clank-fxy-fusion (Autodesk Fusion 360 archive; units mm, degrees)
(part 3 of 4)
sketch "Limit Wire Clip" plane through (0, 0, 0) normal (0, 0, -1) x axis (1, 0, 0)
  line L1 (79.8, -13) -> (66.15, -13)
  line L2 (79.8, -9) -> (79.8, -13)
  line L3 (100.2, -9) -> (79.8, -9)
  line L4 (100.2, -12.5) -> (100.2, -9)
  line L5 (100.7, -13) -> (100.2, -12.5)
  line L6 (102.8, -13) -> (100.7, -13)
  line L7 (102.8, 5.7) -> (102.8, -13)
  line L8 (117, 5.7) -> (102.8, 5.7)
  line L9 (117, 17.5) -> (117, 5.7)
  line L10 (103, 17.5) -> (117, 17.5)
  line L11 (103, 32.35) -> (103, 17.5)
  line L12 (57.65, 32.35) -> (103, 32.35)
  line L13 (57.65, 16.96) -> (57.65, 32.35)
  line L14 (77.0815, 16.46) -> (58.15, 16.46)
  line L15 (58.15, 15.46) -> (77.0815, 15.46)
  line L16 (56.65, 23.55) -> (56.65, 16.96)
  line L17 (2.85, 23.55) -> (56.65, 23.55)
  line L18 (2.85, 8.85) -> (2.85, 23.55)
  line L19 (14.2, 8.85) -> (2.85, 8.85)
  line L20 (14.2, -13) -> (14.2, 8.85)
  line L21 (2.85, -13) -> (14.2, -13)
  line L22 (2.85, -37.1) -> (2.85, -13)
  line L23 (56.65, -37.1) -> (2.85, -37.1)
  line L24 (56.65, -25.4747) -> (56.65, -37.1)
  line L25 (66.15, -25.4747) -> (56.65, -25.4747)
  line L26 (66.15, -13) -> (66.15, -25.4747)
  line L27 (6.5983, -31) -> (11.1017, -31)
  line L28 (4.3467, -27.1) -> (6.5983, -31)
  line L29 (6.5983, -23.2) -> (4.3467, -27.1)
  line L30 (11.1017, -23.2) -> (6.5983, -23.2)
  line L31 (13.3533, -27.1) -> (11.1017, -23.2)
  line L32 (11.1017, -31) -> (13.3533, -27.1)
  line L33 (24.7517, 9.65) -> (27.0033, 13.55)
  line L34 (20.2483, 9.65) -> (24.7517, 9.65)
  line L35 (17.9967, 13.55) -> (20.2483, 9.65)
  line L36 (20.2483, 17.45) -> (17.9967, 13.55)
  line L37 (24.7517, 17.45) -> (20.2483, 17.45)
  line L38 (27.0033, 13.55) -> (24.7517, 17.45)
  line L39 (49.7517, 9.65) -> (52.0033, 13.55)
  line L40 (45.2483, 9.65) -> (49.7517, 9.65)
  line L41 (42.9967, 13.55) -> (45.2483, 9.65)
  line L42 (45.2483, 17.45) -> (42.9967, 13.55)
  line L43 (49.7517, 17.45) -> (45.2483, 17.45)
  line L44 (52.0033, 13.55) -> (49.7517, 17.45)
  line L45 (77.0815, 29.81) -> (73.0815, 29.81)
  line L46 (77.5815, 19.5) -> (77.5815, 29.31)
  line L47 (73.0815, 19) -> (77.0815, 19)
  line L48 (72.5815, 29.31) -> (72.5815, 19.5)
  line L49 (32.7483, 14.65) -> (37.2517, 14.65)
  line L50 (30.4967, 18.55) -> (32.7483, 14.65)
  line L51 (32.7483, 22.45) -> (30.4967, 18.55)
  line L52 (37.2517, 22.45) -> (32.7483, 22.45)
  line L53 (39.5033, 18.55) -> (37.2517, 22.45)
  line L54 (37.2517, 14.65) -> (39.5033, 18.55)
  line L55 (6.5983, 12.3) -> (11.1017, 12.3)
  line L56 (4.3467, 16.2) -> (6.5983, 12.3)
  line L57 (6.5983, 20.1) -> (4.3467, 16.2)
  line L58 (11.1017, 20.1) -> (6.5983, 20.1)
  line L59 (13.3533, 16.2) -> (11.1017, 20.1)
  line L60 (11.1017, 12.3) -> (13.3533, 16.2)
  line L61 (65.6533, -19.4747) -> (63.4017, -15.5747)
  line L62 (63.4017, -23.3747) -> (65.6533, -19.4747)
  line L63 (58.8983, -23.3747) -> (63.4017, -23.3747)
  line L64 (56.6467, -19.4747) -> (58.8983, -23.3747)
  line L65 (58.8983, -15.5747) -> (56.6467, -19.4747)
  line L66 (63.4017, -15.5747) -> (58.8983, -15.5747)
  line L67 (1.35, -31.1) -> (2.85, -31.1)
  line L68 (1.35, -35.1) -> (1.35, -31.1)
  line L69 (-1.95, -37.1) -> (1.85, -37.1)
  line L70 (-1.95, -26.1) -> (-1.95, -37.1)
  line L71 (2.85, -26.1) -> (-1.95, -26.1)
  line L72 (1.85, -35.1) -> (1.35, -35.1)
  line L73 (1.85, -37.1) -> (1.85, -35.1)
  line L74 (79.8, -25.4747) -> (66.15, -25.4747)
  line L75 (79.8, -13) -> (79.8, -25.4747)
  line L76 (79.8, -32) -> (79.8, -25.4747)
  line L77 (56.65, -32) -> (79.8, -32)
  line L78 (80.2, -32) -> (79.8, -32)
  line L79 (80.2, -22) -> (80.2, -32)
  line L80 (79.8, -22) -> (80.2, -22)
  arc A1 centre (58.15, 16.96) radius 0.5 clockwise from (58.15, 16.46) to (57.65, 16.96)
  arc A2 centre (77.0815, 15.96) radius 0.5 clockwise from (77.0815, 16.46) to (77.0815, 15.46)
  arc A3 centre (58.15, 16.96) radius 1.5 clockwise from (58.15, 15.46) to (56.65, 16.96)
  circle C1 centre (66, -6.5) radius 2.125
  circle C2 centre (66, 26.35) radius 2.125
  arc A4 centre (73.0815, 29.31) radius 0.5 clockwise from (72.5815, 29.31) to (73.0815, 29.81)
  arc A5 centre (77.0815, 29.31) radius 0.5 clockwise from (77.0815, 29.81) to (77.5815, 29.31)
  arc A6 centre (77.0815, 19.5) radius 0.5 clockwise from (77.5815, 19.5) to (77.0815, 19)
  arc A7 centre (73.0815, 19.5) radius 0.5 clockwise from (73.0815, 19) to (72.5815, 19.5)
  arc A8 centre (35, -15.45) radius 8.5 clockwise from (43.4011, -16.743) to (26.5989, -14.157)
  arc A9 centre (61.15, -19.4747) radius 34.9579 clockwise from (26.5989, -14.157) to (26.9246, -12.356)
  arc A10 centre (35.2465, -14.0869) radius 8.5 clockwise from (26.9246, -12.356) to (43.5684, -15.8178)
  arc A11 centre (61.15, -19.4747) radius 17.9579 clockwise from (43.4011, -16.743) to (43.5684, -15.8178)
  circle C3 centre (24.0415, -7) radius 2.125
  point P92 (2.85, -31.1)
  point P97 (2.85, -26.1)
  point P30 (2.85, -37.1)
  point P94 (1.85, -37.1)
  point P100 (1.85, -37.1)
  point P33 (66.15, -25.4747)
  point P102 (66.15, -25.4747)
  point P3 (79.8, -13)
  point P104 (79.8, -13)
  point P106 (56.65, -32)
  point P109 (79.8, -22)
  point P93 (1.35, -31.1)
  point P99 (1.85, -35.1)
  point P98 (1.35, -35.1)
  point P107 (80.2, -32)
  point P108 (80.2, -22)
  point P110 (90, -1)
  coincident L22 P92
  perpendicular L22 L67
  perpendicular L67 L68
  perpendicular L68 L69
  perpendicular L69 L70
  coincident L22 P97
  perpendicular L22 L71
  coincident P30 L69
  perpendicular L22 L72
  perpendicular L72 L73
  coincident P94 P100
  coincident P33 P102
  perpendicular L26 L74
  perpendicular L74 L75
  coincident P3 P104
  perpendicular L74 L76
  coincident L24 P106
  perpendicular L24 L77
  perpendicular L76 L78
  perpendicular L78 L79
  coincident L75 P109
  perpendicular L75 L80
  dimension "d1771" distance P30 P97 = 11
  dimension "d1772" distance P92 P93 = 1.5
  dimension "d1773" distance P30 L73 = 1
  dimension "d1774" distance L67 P97 = 5
  dimension "d1775" distance P99 P100 = 2
  dimension "d1776" distance P93 P98 = 4
  dimension "d1777" distance L70 P98 = 3.3
  dimension "d1791" distance P104 L77 = 19
  dimension "d1813" distance P107 P108 = 10
  dimension "d1814" distance L79 P110 = 9.8
extrude "Extrude122" add sketch "Limit Wire Clip" profile of L22 L67 L68 L69 L70 L71 L72 L73 against normal blind 5
extrude "Extrude123" new body sketch "Limit Wire Clip" profile of L1 L24 L25 L26 L74 L75 L76 L77 L78 L79 L80 to an object
chamfer "Chamfer21" distance 1
combine "Combine20"
fillet "Fillet52" radius 0.5
fillet "Fillet57" radius 0.5
fillet "Fillet40" radius 2.2
fillet "Fillet41" radius 2
fillet "Fillet58" radius 1
fillet "Fillet43" radius 1
fillet "Fillet44" radius 5
fillet "Fillet45" radius 2
fillet "Fillet46" radius 1
fillet "Fillet47" radius 2
fillet "Fillet48" radius 1
fillet "Fillet49" radius 2
fillet "Fillet50" radius 1
fillet "Fillet51" radius 2
fillet "Fillet59" radius 0.5
fillet "Fillet60" radius 1
fillet "Fillet61" radius 1
sketch "Motor Cable Clip" plane through (0, 0, 30.7) normal (0, 0, 1) x axis (-1, 0, 0)
  line L1 (-15.084, 6.3745) -> (-14.3541, 20.3023)
  line L2 (-53.5453, 6.1872) -> (-17.3961, 4.2927)
  line L3 (-61.7085, 2.3499) -> (-57.6468, 2.3499)
  line L4 (-66.0474, -6.3422) -> (-63.6058, 0.9823)
  line L5 (-66.15, -23.4747) -> (-66.15, -6.9747)
  line L6 (-58.85, -25.4747) -> (-64.15, -25.4747)
  line L7 (-56.65, -35.1) -> (-56.65, -27.6747)
  line L8 (-4.85, -37.1) -> (-54.65, -37.1)
  line L9 (-2.85, 20.25) -> (-2.85, -35.1)
  line L10 (-13.3555, 21.25) -> (-3.85, 21.25)
  line L11 (-11.85, 2.5624) -> (2.15, -21.6863)
  line L12 (-5.7878, 6.0624) -> (-11.85, 2.5624)
  line L13 (8.2122, -18.1863) -> (-5.7878, 6.0624)
  line L14 (2.15, -21.6863) -> (8.2122, -18.1863)
  line L15 (-13.85, 5.7) -> (-13.85, -36.6)
  line L16 (-1.5517, -23.8235) -> (2.15, -21.6863)
  line L17 (-11.85, 2.5624) -> (-11.85, -19.6838)
  line L18 (-2.85, -24.573) -> (-1.5517, -23.8235)
  arc A1 centre (-13.3555, 20.25) radius 1 clockwise from (-14.3541, 20.3023) to (-13.3555, 21.25)
  arc A2 centre (-17.281, 6.4897) radius 2.2 clockwise from (-15.084, 6.3745) to (-17.3961, 4.2927)
  arc A3 centre (-61.7085, 0.3499) radius 2 clockwise from (-63.6058, 0.9823) to (-61.7085, 2.3499)
  arc A4 centre (-64.15, -6.9747) radius 2 clockwise from (-66.15, -6.9747) to (-66.0474, -6.3422)
  arc A5 centre (-64.15, -23.4747) radius 2 clockwise from (-64.15, -25.4747) to (-66.15, -23.4747)
  arc A6 centre (-58.85, -27.6747) radius 2.2 clockwise from (-58.85, -25.4747) to (-56.65, -27.6747)
  arc A7 centre (-54.65, -35.1) radius 2 clockwise from (-54.65, -37.1) to (-56.65, -35.1)
  arc A8 centre (-4.85, -35.1) radius 2 clockwise from (-2.85, -35.1) to (-4.85, -37.1)
  arc A9 centre (-3.85, 20.25) radius 1 clockwise from (-3.85, 21.25) to (-2.85, 20.25)
  circle C1 centre (-61.15, -19.4747) radius 2.125
  arc A10 centre (-9.3208, -29.8267) radius 2.125 clockwise from (-7.2369, -30.2429) to (-11.4046, -29.4105)
  arc A11 centre (-61.15, -19.4747) radius 50.728 clockwise from (-10.9528, -26.7934) to (-11.4046, -29.4105)
  arc A12 centre (-8.85, -27.1) radius 2.125 clockwise from (-10.9528, -26.7934) to (-6.7472, -27.4066)
  arc A13 centre (-61.15, -19.4747) radius 54.978 clockwise from (-6.7472, -27.4066) to (-7.2369, -30.2429)
  circle C2 centre (-19.5, 0.05) radius 1.625
  circle C3 centre (-35, -15.45) radius 11.05
  circle C4 centre (-19.5, -30.95) radius 1.625
  circle C5 centre (-50.5, 0.05) radius 1.625
  arc A14 centre (-7.0546, 13.4139) radius 2.125 clockwise from (-5.2389, 14.5179) to (-8.8704, 12.31)
  arc A15 centre (-61.15, -19.4747) radius 61.1836 clockwise from (-10.6055, 15.0026) to (-8.8704, 12.31)
  arc A16 centre (-8.85, 16.2) radius 2.125 clockwise from (-10.6055, 15.0026) to (-7.0945, 17.3974)
  arc A17 centre (-61.15, -19.4747) radius 65.4336 clockwise from (-7.0945, 17.3974) to (-5.2389, 14.5179)
  circle C6 centre (-50.5, -30.95) radius 1.625
  arc A18 centre (-8.85, -27.1) radius 8 clockwise from (-11.85, -19.6838) to (-1.5517, -23.8235)
  arc A19 centre (-8.85, -27.1) radius 5 clockwise from (-13.7977, -26.3786) to (-3.9023, -27.8214)
  arc A20 centre (-53.65, 4.1899) radius 2 clockwise from (-55.6484, 4.2699) to (-53.5453, 6.1872)
  arc A21 centre (-57.6468, 4.3499) radius 2 clockwise from (-55.6484, 4.2699) to (-57.6468, 2.3499)
  point P49 (-8.85, -27.1)
  point P59 (-8.85, -27.1)
  point P61 (-2.85, -24.573)
  point P50 (-7.0546, 13.4139)
  point P53 (-11.85, 2.5624)
  point P52 (2.15, -21.6863)
  point P55 (8.2122, -18.1863)
  perpendicular L11 L12
  parallel L11 L13
  parallel L12 L14
  perpendicular L11 L16
  coincident P49 P59
  vertical L17
  coincident L9 P61
  parallel L16 L18
  dimension "d1818" angle L9 L13 = 30
  dimension "d1819" distance P50 L12 = 7
  dimension "d1820" distance P53 L15 = 2
  dimension "d1822" distance P52 P55 = 7
  dimension "d1823" distance P52 P53 = 28
  dimension "d1854" distance A18 A19 = 3
extrude "Extrude127" add sketch "Motor Cable Clip" profile of L9 L11 L13 L14 L16 A18 L18 to an object
extrude "Extrude128" add sketch "Motor Cable Clip" profile of L9 L11 L12 L13 L14 L16 A18 L17 along normal blind 51
sketch "Sketch32" plane through (1.7158, 0.9906, 0) normal (-0.866, -0.5, 0) x axis (0.5, -0.866, 0)
  line L1 (2.2685, 24.7) -> (-19.8559, 24.7)
  line L2 (2.2685, 30.7) -> (2.2685, 24.7)
  line L3 (8.1441, 30.7) -> (2.2685, 30.7)
  line L4 (8.1441, 81.7) -> (8.1441, 30.7)
  line L5 (-19.8559, 81.7) -> (8.1441, 81.7)
  line L6 (-19.8559, 24.7) -> (-19.8559, 81.7)
  line L7 (-1.8559, 34.2) -> (-1.8559, 78.2)
  circle C1 centre (-1.8559, 78.2) radius 1.35
  circle C2 centre (-1.8559, 34.2) radius 1.35
  point P8 (-1.8559, 78.2)
  point P10 (-1.8559, 78.2)
  point P9 (-1.8559, 34.2)
  point P11 (-1.8559, 34.2)
  point P6 (8.1441, 81.7)
  vertical L7
  coincident P8 P10
  coincident P9 P11
  equal C1 C2
  dimension "d2013" distance P8 P9 = 44
  dimension "d2014" diameter C1 = 2.7
  dimension "d2015" distance L5 P10 = 3.5
  dimension "d2016" distance P6 L7 = 10
extrude "Extrude137" cut sketch "Sketch32" profile of C1 C2 to an object
fillet "Fillet69" radius 2
chamfer "Chamfer18" distance 2
component_insert "Component Insert72"
joint "Assemble72" alignAngle 0 alignOffsetX 0 alignOffsetY 0 alignOffsetZ 0
component_insert "Component Insert73"
joint "Assemble73" alignAngle 0 alignOffsetX 0 alignOffsetY 0 alignOffsetZ -17.5
component_insert "Component Insert74"
joint "Assemble74" alignAngle 0 alignOffsetX 0 alignOffsetY 0 alignOffsetZ 0
component_insert "Component Insert75"
joint "Assemble75" alignAngle 0 alignOffsetX 0 alignOffsetY 0 alignOffsetZ 0
component_insert "Component Insert76"
joint "Assemble76" alignAngle 0 alignOffsetX 0 alignOffsetY 0 alignOffsetZ 0
component_insert "Component Insert77"
joint "Assemble77" alignAngle 0 alignOffsetX 0 alignOffsetY 0 alignOffsetZ 0
component_insert "Component Insert79"
joint "Assemble79" alignAngle 30 alignOffsetX 0 alignOffsetY 0 alignOffsetZ -1.5
component_insert "Component Insert80"
joint "Assemble80" alignAngle 0 alignOffsetX 0 alignOffsetY 0 alignOffsetZ 0
component_insert "Component Insert81"
joint "Assemble81" alignAngle 0 alignOffsetX 0 alignOffsetY 0 alignOffsetZ 0
component_insert "Component Insert82"
joint "Assemble82" alignAngle 0 alignOffsetX 0 alignOffsetY 0 alignOffsetZ 0
component_insert "Component Insert78"
joint "Assemble78" alignAngle 30 alignOffsetX 0 alignOffsetY 0 alignOffsetZ -1.5
component_insert "Component Insert85"
joint "Assemble84" alignAngle 0 alignOffsetX 0 alignOffsetY 0 alignOffsetZ 0
component_insert "Component Insert84"
joint "Assemble85" alignAngle 0 alignOffsetX 0 alignOffsetY 0 alignOffsetZ 0
component_insert "Component Insert86"
joint "Assemble86" alignAngle 0 alignOffsetX 0 alignOffsetY 0 alignOffsetZ 0
component_insert "Component Insert87"
joint "Assemble87" alignAngle 0 alignOffsetX 0 alignOffsetY 0 alignOffsetZ 0
component_insert "Component Insert88"
joint "Assemble88" alignAngle 0 alignOffsetX 0 alignOffsetY 0 alignOffsetZ 0
component_insert "Component Insert89"
joint "Assemble89" alignAngle 0 alignOffsetX 0 alignOffsetY 0 alignOffsetZ 0
component_insert "Component Insert92"
joint "Assemble92" alignAngle 0 alignOffsetX 0 alignOffsetY 0 alignOffsetZ 0
component_insert "Component Insert93"
joint "Assemble93" alignAngle 0 alignOffsetX 0 alignOffsetY 0 alignOffsetZ 0
component_insert "Component Insert94"
joint "Assemble94" alignAngle 0 alignOffsetX 0 alignOffsetY 0 alignOffsetZ 0
component_insert "Component Insert95"
joint "Assemble95" alignAngle 0 alignOffsetX 0 alignOffsetY 0 alignOffsetZ 0
component_insert "Component Insert96"
joint "Assemble96" alignAngle 0 alignOffsetX 0 alignOffsetY 0 alignOffsetZ 0
component_insert "Component Insert97"
joint "Assemble97" alignAngle 0 alignOffsetX 0 alignOffsetY 0 alignOffsetZ 0
component_insert "Component Insert98"
joint "Assemble98" alignAngle 0 alignOffsetX 0 alignOffsetY 0 alignOffsetZ 0
component_insert "Component Insert99"
joint "Assemble99" alignAngle 0 alignOffsetX 0 alignOffsetY 0 alignOffsetZ 0
component_insert "Component Insert107"
joint "Assemble107" alignAngle 25 alignOffsetX 0 alignOffsetY 0 alignOffsetZ 0
component_insert "Component Insert108"
joint "Assemble108" alignAngle 0 alignOffsetX 0 alignOffsetY 0 alignOffsetZ 0
component_insert "Component Insert100"
joint "Assemble100" alignAngle 0 alignOffsetX 0 alignOffsetY 0 alignOffsetZ 0
component_insert "Component Insert101"
joint "Assemble101" alignAngle -90 alignOffsetX 0 alignOffsetY 0 alignOffsetZ 0
component_insert "Component Insert102"
joint "Assemble102" alignAngle -90 alignOffsetX 0 alignOffsetY 0 alignOffsetZ 0
component_insert "Component Insert103"
joint "Assemble103" alignAngle -90 alignOffsetX 0 alignOffsetY 0 alignOffsetZ 0
component_insert "Component Insert104"
joint "Assemble104" alignAngle -30 alignOffsetX 0 alignOffsetY 0 alignOffsetZ 0
component_insert "Component Insert105"
joint "Assemble105" alignAngle 180 alignOffsetX 0 alignOffsetY 0 alignOffsetZ 0
component_insert "Component Insert106"
joint "Assemble106" alignAngle 180 alignOffsetX 0 alignOffsetY 0 alignOffsetZ 0
component_insert "Component Insert109"
component_insert "Component Insert110"
component_insert "Component Insert111"
component_insert "Component Insert112"
component_insert "Component Insert113"
joint "Assemble109" alignAngle 30 alignOffsetX 0 alignOffsetY 0 alignOffsetZ -1.5
joint "Assemble110" alignAngle 30 alignOffsetX 0 alignOffsetY 0 alignOffsetZ -1.5
joint "Assemble111" alignAngle 30 alignOffsetX 0 alignOffsetY 0 alignOffsetZ 0
joint "Assemble112" alignAngle 0 alignOffsetX 0 alignOffsetY 0 alignOffsetZ 0
joint "Assemble113" alignAngle 0 alignOffsetX 0 alignOffsetY 0 alignOffsetZ 0
component_insert "Component Insert114"
joint "Assemble114" alignAngle 30 alignOffsetX 0 alignOffsetY 0 alignOffsetZ 0
component_insert "Component Insert115"
component_insert "Component Insert116"
joint "Assemble115" alignAngle 30 alignOffsetX 0 alignOffsetY 0 alignOffsetZ 0
joint "Assemble116" alignAngle 30 alignOffsetX 0 alignOffsetY 0 alignOffsetZ -1.5
component_insert "Component Insert117"
component_insert "Component Insert119"
component_insert "Component Insert120"
joint "Assemble117" alignAngle 0 alignOffsetX 0 alignOffsetY 0 alignOffsetZ 0
joint "Assemble118" alignAngle 0 alignOffsetX 0 alignOffsetY 0 alignOffsetZ 0
joint "Assemble119" alignAngle 0 alignOffsetX 0 alignOffsetY 0 alignOffsetZ 0
component_insert "Component Insert121"
component_insert "Component Insert122"
component_insert "Component Insert123"
joint "Assemble120" alignAngle 0 alignOffsetX 0 alignOffsetY 0 alignOffsetZ 0
joint "Assemble121" alignAngle 0 alignOffsetX 0 alignOffsetY 0 alignOffsetZ 0
joint "Assemble122" alignAngle 0 alignOffsetX 0 alignOffsetY 0 alignOffsetZ 0
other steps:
joint_origin "JointOrigin41"
joint_origin "JointOrigin43"
joint_origin "JointOrigin44"
joint_origin "JointOrigin45"
joint_origin "JointOrigin46"
joint_origin "JointOrigin47"
joint_origin "JointOrigin48"
joint_origin "JointOrigin49"
joint_origin "JointOrigin50"
joint_origin "JointOrigin52"
joint_origin "JointOrigin53"
joint_origin "JointOrigin54"
joint_origin "JointOrigin57"
joint_origin "JointOrigin58"
joint_origin "JointOrigin59"
joint_origin "JointOrigin60"
joint_origin "JointOrigin61"
joint_origin "JointOrigin62"
joint_origin "JointOrigin63"
joint_origin "JointOrigin65"
joint_origin "JointOrigin66"
joint_origin "JointOrigin67"
joint_origin "JointOrigin68"
joint_origin "JointOrigin69"
joint_origin "JointOrigin70"
joint_origin "JointOrigin71"
joint_origin "JointOrigin72"
joint_origin "JointOrigin73"
joint_origin "JointOrigin74"
joint_origin "JointOrigin75"
joint_origin "JointOrigin76"
joint_origin "JointOrigin77"
joint_origin "JointOrigin78"
joint_origin "JointOrigin79"
joint_origin "JointOrigin80"
joint_origin "JointOrigin81"
joint_origin "JointOrigin82"
joint_origin "JointOrigin83"
named bodies: "Top Plate", "Side Plate", "Motor Plate", "Idler Catch", "Belt Pinch"

design "HW_M4-Nylock"
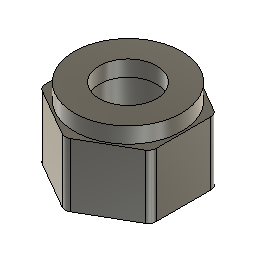
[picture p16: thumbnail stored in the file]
sketch "Sketch1" plane through (0, 0, 0) normal (0, 0, 1) x axis (1, 0, 0)
  line L1 (0, 4.0415) -> (3.5, 2.0207)
  line L2 (-3.5, 2.0207) -> (0, 4.0415)
  line L3 (-3.5, -2.0207) -> (-3.5, 2.0207)
  line L4 (0, -4.0415) -> (-3.5, -2.0207)
  line L5 (3.5, -2.0207) -> (0, -4.0415)
  line L6 (3.5, 2.0207) -> (3.5, -2.0207)
  circle C1 centre (0, 0) radius 2.05
  circle C2 centre (0, 0) radius 3.375
  circle C3 centre (0, 0) radius 1.8
  point P1 (0, 0)
  point P8 (0, 0)
  point P9 (0, 0)
  point P4 (-3.5, 2.0207)
  coincident P1 P8
  vertical L6
  coincident P8 P9
  concentric C1 C2
  concentric C1 C3
  dimension "d1" distance P4 L6 = 7
  dimension "d2" diameter C1 = 4.1
  dimension "d5" diameter C2 = 6.75 (= "d1 - 0.25 mm")
  dimension "d9" distance C1 C3 = 0.25
extrude "Extrude1" new body sketch "Sketch1" profile of L1 L2 L3 L4 L5 L6 C1 C2 along normal blind 4
extrude "Extrude2" sketch "Sketch1" profile of C1 C2 C3 blind 1
fillet "Fillet1" radius 0.5

design "CT_UCBus-3010"
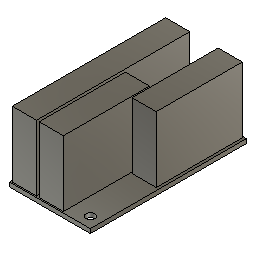
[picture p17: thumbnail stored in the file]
sketch "Sketch1" plane through (0, 0, 0) normal (0, 0, 1) x axis (1, 0, 0)
  line L1 (30, 0) -> (0, 0)
  line L2 (30, 58) -> (30, 0)
  line L3 (0, 0) -> (0, 58)
  line L4 (9.5, 57.5) -> (0.5, 57.5)
  line L5 (9.5, 0.5) -> (9.5, 57.5)
  line L6 (0.5, 0.5) -> (9.5, 0.5)
  line L7 (0.5, 57.5) -> (0.5, 0.5)
  line L8 (0, 58) -> (30, 58)
  line L9 (7.5, 48) -> (2.5, 48)
  line L10 (7.5, 10) -> (7.5, 48)
  line L11 (2.5, 10) -> (7.5, 10)
  line L12 (2.5, 48) -> (2.5, 10)
  line L13 (9.5, 57.5) -> (0.5, 0.5)
  line L14 (7.5, 10) -> (2.5, 48)
  line L15 (12.5, 10) -> (17.5, 10)
  line L16 (17.5, 10) -> (17.5, 23)
  line L17 (12.5, 23) -> (12.5, 10)
  line L18 (17.5, 23) -> (12.5, 23)
  line L19 (19.5, 32.5) -> (10.5, 0.5)
  line L20 (10.5, 0.5) -> (19.5, 0.5)
  line L21 (10.5, 32.5) -> (10.5, 0.5)
  line L22 (17.5, 10) -> (12.5, 23)
  line L23 (19.5, 32.5) -> (10.5, 32.5)
  line L24 (19.5, 0.5) -> (19.5, 32.5)
  line L25 (22, 35) -> (27, 35)
  line L26 (20, 25.5) -> (29, 25.5)
  line L27 (27, 48) -> (22, 48)
  line L28 (27, 35) -> (22, 48)
  line L29 (22, 48) -> (22, 35)
  line L30 (27, 35) -> (27, 48)
  line L31 (20, 57.5) -> (20, 25.5)
  line L32 (29, 57.5) -> (20, 25.5)
  line L33 (29, 25.5) -> (29, 57.5)
  line L34 (29, 57.5) -> (20, 57.5)
  circle C1 centre (14, 54) radius 1.625
  circle C2 centre (26, 4) radius 1.625
  point P1 (0, 0)
  point P2 (0, 0)
  point P4 (30, 58)
  point P5 (0, 58)
  point P6 (14, 54)
  point P10 (9.5, 0.5)
  point P11 (0.5, 0.5)
  point P8 (0.5, 57.5)
  point P12 (2.5, 48)
  point P15 (2.5, 10)
  point P13 (7.5, 48)
  point P7 (26, 4)
  point P16 (10.5, 0.5)
  point P17 (19.5, 0.5)
  point P19 (10.5, 32.5)
  point P22 (12.5, 23)
  point P23 (12.5, 10)
  point P20 (17.5, 23)
  point P26 (20, 25.5)
  point P28 (29, 25.5)
  point P24 (20, 57.5)
  point P25 (22, 35)
  point P27 (22, 48)
  point P29 (27, 48)
  point P31 (29, 57.5)
  horizontal L1
  vertical L2
  horizontal L8
  vertical L3
  coincident P1 P2
  equal C1 C2
  horizontal L4
  vertical L5
  horizontal L6
  vertical L7
  horizontal L9
  vertical L10
  horizontal L11
  vertical L12
  midpoint L13 L14
  horizontal L23
  vertical L24
  horizontal L20
  vertical L21
  horizontal L18
  vertical L16
  horizontal L15
  vertical L17
  midpoint L19 L22
  horizontal L34
  vertical L33
  horizontal L26
  vertical L31
  horizontal L27
  vertical L30
  horizontal L25
  vertical L29
  midpoint L28 L32
  dimension "d1" distance P4 P5 = 30
  dimension "d2" distance P2 P5 = 58
  dimension "d3" distance P6 L8 = 4
  dimension "d6" diameter C1 = 3.25
  dimension "d7" distance L3 P6 = 14
  dimension "d11" distance P10 P11 = 9
  dimension "d12" distance P8 P11 = 57
  dimension "d21" distance P12 P15 = 38
  dimension "d22" distance P12 P13 = 5
  dimension "d25" distance L1 P7 = 4
  dimension "d31" distance P16 P17 = 9
  dimension "d32" distance P16 P19 = 32
  dimension "d33" distance P22 P23 = 13
  dimension "d34" distance P20 P22 = 5
  dimension "d35" distance P8 L8 = 0.5
  dimension "d36" distance L3 P8 = 0.5
  dimension "d39" distance P26 P28 = 9
  dimension "d40" distance P24 P26 = 32
  dimension "d41" distance P25 P27 = 13
  dimension "d42" distance P27 P29 = 5
  dimension "d45" distance L24 P24 = 0.5
  dimension "d47" distance L2 P28 = 1
  dimension "d48" distance L2 P7 = 4
  dimension "d49" distance L1 P17 = 0.5
  dimension "d50" distance L8 P31 = 0.5
extrude "Extrude1" new body sketch "Sketch1" profile of L1 L2 L8 L3 C1 C2 L4 L5 L6 L7 along normal blind 1.6
extrude "Extrude2" add sketch "Sketch1" profile of L4 L5 L6 L7 L9 L10 L11 L12 L15 L16 L17 L18 L20 L21 L23 L24 L25 L26 L27 L29 L30 L31 L33 L34 along normal blind 26
extrude "Extrude3" add sketch "Sketch1" profile of L9 L10 L11 L12 L15 L16 L17 L18 L25 L27 L29 L30 against normal blind 2

design "AS_FXY-YLB" references "AS_Pinched-Roller", "HW_M4x25-FHCS", "HW_M4x40-FHCS", "HW_M4-Nylock", "HW_M4x14-FHCS", "AS_YLB-Wiring-Mount", "AS_Single-Roller"
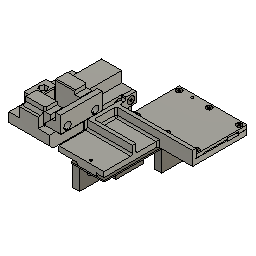
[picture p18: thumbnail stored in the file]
parameter "t_sheet_MAIN" = 7.9375
parameter "extrusion_w" = 20
parameter "extrusion_h" = 60
parameter "r_cutoutTool" = 2.05 (= "4.1 mm / 2")
parameter "od_bearings" = 13
parameter "id_bearings" = 4
parameter "t_bearings" = 5
parameter "preload" = 0.15
parameter "hw_m3_thru" = 3.5
parameter "hw_m3_thread" = 2.5
parameter "hw_m3_head" = 5.5
parameter "hw_m3_headheight" = 3
parameter "hw_m3_flathead" = 6
parameter "hw_m3_buttonhead" = 5.7
parameter "hw_m3_washer" = 7
parameter "hw_m3hex_d" = 5.5
parameter "hw_m3hex_t" = 4
parameter "hw_m3i_d" = 5.4
parameter "hw_m3i_l" = 3.8
parameter "hw_m3ichamfer" = 0.95 (= "( hw_m3i_d - hw_m3_thru ) / 2")
parameter "hw_m4_thru" = 4.25
parameter "hw_m4_head" = 7
parameter "hw_m4_headheight" = 4
parameter "hw_m4hex_d" = 7
parameter "hw_m4hex_t" = 5.2
parameter "hw_m4i_d" = 6
parameter "hw_m4i_l" = 4.8
parameter "hw_m4ichamfer" = 0.875 (= "( hw_m4i_d - hw_m4_thru ) / 2")
parameter "hw_m5_thread" = 4.2
parameter "hw_m5_head" = 8.5
parameter "hw_m5_washer" = 10
parameter "hw_m5_thru" = 5.25
parameter "hw_m6_thru" = 6.5
parameter "hw_m6_head" = 10
parameter "hw_m6_flathead" = 12
parameter "hw_m6_buttonhead" = 10.5
parameter "hw_m6_washer" = 12
parameter "p_belt" = 2
parameter "w_belt" = 10
parameter "t_belt" = 1.4
parameter "belt_pdo_toothside" = 1.15
parameter "belt_pdo_backside" = 0.25
parameter "flex_t" = 3.3
parameter "flex_l" = 5.5
sketch "Facing" plane through (0, 0, 0) normal (0, 0, 1) x axis (1, 0, 0)
  line L1 (10.075, -10.075) -> (-10.075, -10.075)
  line L2 (10.075, 10.075) -> (10.075, -10.075)
  line L3 (-10.075, 10.075) -> (10.075, 10.075)
  line L4 (-10.075, -10.075) -> (-10.075, 10.075)
  line L5 (-11.75, 22.5) -> (-13.15, 22.5)
  line L6 (-11.75, 33.5) -> (-11.75, 22.5)
  line L7 (-13.15, 33.5) -> (-11.75, 33.5)
  line L8 (-13.15, 22.5) -> (-13.15, 33.5)
  line L9 (-12, 22.5) -> (-12, 33.5)
  line L10 (23.35, 42.5) -> (23.35, -30)
  line L11 (-11.65, 42.5) -> (23.35, 42.5)
  line L12 (-23.5, 13.3) -> (-23.5, -30)
  line L13 (-12, 42.5) -> (-12, 33.5)
  line L14 (-23.5, 42.5) -> (-12, 42.5)
  line L15 (-23.5, 13.5) -> (-23.5, 42.5)
  line L16 (-12, 13.5) -> (-23.5, 13.5)
  line L17 (-12, 22.5) -> (-12, 13.5)
  line L18 (-11.65, 13.3) -> (-23.5, 13.3)
  line L19 (-11.65, 42.5) -> (-11.65, 13.3)
  line L20 (10.075, -10.075) -> (-10.075, 10.075)
  line L21 (-23.5, -30) -> (23.35, -30)
  line L22 (-12.4585, 2.465) -> (-14.4793, -1.035)
  line L23 (-20.5415, 2.465) -> (-18.5207, 5.965)
  line L24 (-14.4793, 5.965) -> (-12.4585, 2.465)
  line L25 (-14.4793, -1.035) -> (-18.5207, -1.035)
  line L26 (-18.5207, -1.035) -> (-20.5415, 2.465)
  line L27 (-18.5207, 5.965) -> (-14.4793, 5.965)
  line L28 (20.3915, 2.465) -> (18.3707, -1.035)
  line L29 (12.3085, 2.465) -> (14.3293, 5.965)
  line L30 (18.3707, 5.965) -> (20.3915, 2.465)
  line L31 (18.3707, -1.035) -> (14.3293, -1.035)
  line L32 (14.3293, -1.035) -> (12.3085, 2.465)
  line L33 (14.3293, 5.965) -> (18.3707, 5.965)
  line L34 (16.35, 2.465) -> (-16.5, 2.465)
  line L35 (20.05, -3.575) -> (12.6085, -3.575)
  line L36 (20.05, -9.075) -> (20.05, -3.575)
  line L37 (12.6085, -9.075) -> (20.05, -9.075)
  line L38 (12.6085, -3.575) -> (12.6085, -9.075)
  line L39 (9.3085, 9.075) -> (23.35, 9.075)
  line L40 (9.3085, -9.075) -> (9.3085, 9.075)
  line L41 (8.3085, -9.075) -> (9.3085, -9.075)
  line L42 (8.3085, 10.075) -> (8.3085, -9.075)
  line L43 (23.35, 10.075) -> (8.3085, 10.075)
  line L44 (10.075, 42.5) -> (10.075, 10.075)
  line L45 (10.075, -30) -> (10.075, -10.075)
  line L46 (23.35, -10.075) -> (10.075, -10.075)
  line L47 (8.3085, -10.075) -> (8.3085, -9.075)
  line L48 (-11.65, 12.5) -> (-11.65, 13.3)
  line L49 (-23.5, 12.5) -> (-11.65, 12.5)
  line L50 (-11.65, -12.5) -> (-11.65, -30)
  line L51 (-23.5, -12.5) -> (-11.65, -12.5)
  circle C1 centre (0, 0) radius 2.75
  circle C2 centre (-16.5, 2.465) radius 2.125
  circle C3 centre (-16.5, 2.465) radius 6.5
  circle C4 centre (16.35, 2.465) radius 2.125
  circle C5 centre (16.35, 2.465) radius 6.5
  point P10 (-12, 33.5)
  point P11 (-12, 22.5)
  point P12 (-12, 28)
  point P3 (10.075, -10.075)
  point P13 (10.075, -10.075)
  point P23 (-12, 22.5)
  point P17 (-11.65, 42.5)
  point P25 (-11.65, 42.5)
  point P19 (-12, 42.5)
  point P21 (-23.5, 13.5)
  point P26 (0, 0)
  point P14 (-23.5, -30)
  point P27 (-23.5, -30)
  point P29 (-16.5, 2.465)
  point P36 (-16.5, 2.465)
  point P33 (-16.5, 2.465)
  point P39 (16.35, 2.465)
  point P46 (16.35, 2.465)
  point P43 (16.35, 2.465)
  point P48 (-16.5, 2.465)
  point P49 (16.35, 2.465)
  point P54 (23.35, 9.075)
  point P60 (23.35, 10.075)
  point P53 (12.6085, -9.075)
  point P1 (0, 0)
  point P55 (9.3085, 9.075)
  point P56 (9.3085, 9.075)
  point P4 (10.075, 10.075)
  point P62 (10.075, -30)
  point P61 (10.075, 42.5)
  point P63 (23.35, -10.075)
  point P64 (8.3085, -10.075)
  point P66 (-23.5, 12.5)
  point P67 (-11.65, -30)
  point P69 (-23.5, -12.5)
  point P65 (-11.65, 12.5)
  point P2 (-10.075, -10.075)
  point P5 (-10.075, 10.075)
  point P6 (-13.15, 22.5)
  point P9 (-13.15, 33.5)
  point P8 (-11.75, 33.5)
  point P22 (-12, 13.5)
  point P30 (-18.5207, 5.965)
  point P32 (-16.5, 2.465)
  point P40 (14.3293, 5.965)
  point P42 (16.35, 2.465)
  point P51 (20.05, -3.575)
  point P52 (20.05, -9.075)
  point P45 (18.3707, -1.035)
  point P50 (12.6085, -3.575)
  point P44 (12.3085, 2.465)
  horizontal L1
  vertical L2
  horizontal L3
  vertical L4
  horizontal L5
  vertical L6
  horizontal L7
  vertical L8
  coincident L7 P10
  coincident L5 P11
  perpendicular L5 L9
  midpoint L9 P12
  coincident P3 P13
  perpendicular L2 L11
  perpendicular L7 L13
  perpendicular L9 L14
  perpendicular L7 L15
  perpendicular L15 L16
  perpendicular L16 L17
  coincident P11 P23
  perpendicular L12 L18
  perpendicular L18 L19
  coincident P17 P25
  coincident L11 P19
  coincident L12 P21
  vertical L12
  midpoint P26 L20
  vertical L10
  perpendicular L10 L21
  coincident P14 P27
  concentric C2 C3
  coincident P29 P36
  coincident P33 P36
  horizontal L25
  concentric C4 C5
  coincident P39 P46
  coincident P43 P46
  horizontal L31
  coincident P33 P48
  coincident P46 P49
  horizontal L34
  horizontal L35
  vertical L36
  horizontal L37
  vertical L38
  coincident L10 P54
  perpendicular L10 L39
  perpendicular L39 L40
  perpendicular L2 L41
  perpendicular L41 L42
  coincident L10 P60
  perpendicular L10 L43
  coincident P53 L41
  coincident P1 P26
  coincident P55 P56
  coincident P4 L43
  perpendicular L43 L44
  perpendicular L1 L45
  coincident L21 P62
  coincident L11 P61
  coincident L10 P63
  perpendicular L10 L46
  coincident L1 P64
  perpendicular L1 L47
  perpendicular L18 L48
  coincident L12 P66
  perpendicular L12 L49
  coincident L21 P67
  perpendicular L21 L50
  coincident L12 P69
  perpendicular L12 L51
  coincident P65 L50
  dimension "d43" distance P2 P5 = 20.15 (= "d44")
  dimension "d44" distance P4 P5 = 20.15
  dimension "d45" distance P6 P9 = 11
  dimension "d46" distance P8 L9 = 0.25 (= "belt_pdo_backside")
  dimension "d47" distance P9 L6 = 1.4 (= "t_belt")
  dimension "d51" distance P8 L19 = 0.1
  dimension "d52" distance P22 L18 = 0.2
  dimension "d54" distance P10 P19 = 9
  dimension "d55" distance P22 P23 = 9
  dimension "d71" diameter C1 = 5.5
  dimension "d102" distance P5 L18 = 3.225
  dimension "d206" diameter C3 = 13 (= "od_bearings")
  dimension "d207" diameter C2 = 4.25
  dimension "d208" distance P30 L22 = 7 (= "hw_m4hex_d")
  dimension "d161" distance P26 P32 = 16.5 (= "extrusion_w / 2 + od_bearings / 2")
  dimension "d162" distance L12 P32 = 7 (= "od_bearings / 2 + 0.5 mm")
  dimension "d163" diameter C5 = 13 (= "od_bearings")
  dimension "d164" diameter C4 = 4.25
  dimension "d165" distance P40 L28 = 7 (= "hw_m4hex_d")
  dimension "d166" distance P48 P49 = 32.85 (= "extrusion_w + od_bearings - preload")
  dimension "d167" distance L10 P42 = 7 (= "od_bearings / 2 + 0.5 mm")
  dimension "d171" distance P51 P52 = 5.5 (= "flex_l")
  dimension "d174" distance L10 L36 = 3.3 (= "flex_t")
  dimension "d175" distance P45 L35 = 2.54
  dimension "d177" distance P54 L43 = 1
  dimension "d178" distance L40 L42 = 1
  dimension "d179" distance P50 L40 = 3.3 (= "flex_t")
  dimension "d181" distance P44 L40 = 3
  dimension "d202" distance P13 L37 = 1
  dimension "d239" distance P26 L21 = 30
  dimension "d240" distance P26 L51 = 12.5
  dimension "d241" distance P1 L49 = 12.5 (= "d240")
  dimension "d553" distance P12 P26 = 28
  dimension "d554" distance P1 P12 = 12
extrude "Extrude13" new body sketch "Facing" profile of L1 L2 L3 L4 L10 L11 L12 L18 L19 C1 L21 L22 C2 L23 L24 L25 L26 L27 L28 C4 L29 L30 L31 L32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 along normal blind 9.5
chamfer "Chamfer22" distance 3
sketch "Z Belt Guide" plane through (0, 0, 0) normal (1, 0, 0) x axis (0, 1, 0)
  line L1 (-30.075, 15) -> (70.075, 15)
  line L2 (10.075, 0) -> (10.075, 62.3598)
  line L3 (-10.075, 64.0764) -> (-10.075, 0)
  line L4 (-30.075, 14.75) -> (70.075, 14.75)
  line L5 (70.075, 16.15) -> (-30.075, 16.15)
  line L6 (70.075, 27.9824) -> (70.075, 14.75)
  line L7 (-30.075, 26.5824) -> (70.075, 26.5824)
  line L8 (-30.075, 27.9824) -> (70.075, 27.9824)
  line L9 (-30.075, 27.7324) -> (70.075, 27.7324)
  line L10 (-30.075, 27.9824) -> (-30.075, 14.75)
  line L11 (16, 24.5415) -> (19.5, 22.5207)
  line L12 (12.5, 22.5207) -> (16, 24.5415)
  line L13 (12.5, 18.4793) -> (12.5, 22.5207)
  line L14 (16, 16.4585) -> (12.5, 18.4793)
  line L15 (19.5, 18.4793) -> (16, 16.4585)
  line L16 (19.5, 22.5207) -> (19.5, 18.4793)
  line L17 (-19.5, 22.5207) -> (-16, 24.5415)
  line L18 (-12.5, 22.5207) -> (-12.5, 18.4793)
  line L19 (-16, 24.5415) -> (-12.5, 22.5207)
  line L20 (-16, 16.4585) -> (-19.5, 18.4793)
  line L21 (-19.5, 18.4793) -> (-19.5, 22.5207)
  line L22 (-12.5, 18.4793) -> (-16, 16.4585)
  line L23 (16, 20.5) -> (-16, 20.5)
  line L24 (24, 14.75) -> (24, 27.9824)
  line L25 (-24, 14.75) -> (-24, 27.9824)
  circle C1 centre (16, 20.5) radius 2.375
  circle C2 centre (16, 20.5) radius 4
  circle C3 centre (-16, 20.5) radius 2.375
  circle C4 centre (-16, 20.5) radius 4
  point P1 (0, 0)
  point P7 (-10.075, 0)
  point P6 (10.075, 0)
  point P9 (10.075, 0)
  point P10 (-10.075, 0)
  point P2 (70.075, 15)
  point P14 (70.075, 16.15)
  point P16 (70.075, 26.5824)
  point P19 (70.075, 27.7324)
  point P18 (-30.075, 27.9824)
  point P21 (-30.075, 27.9824)
  point P20 (-30.075, 27.7324)
  point P17 (-30.075, 26.5824)
  point P3 (-30.075, 15)
  point P13 (-30.075, 16.15)
  point P22 (16, 20.5)
  point P30 (16, 20.5)
  point P31 (-16, 20.5)
  point P39 (-16, 20.5)
  point P36 (-16, 20.5)
  point P40 (-16, 20.5)
  point P41 (16, 20.5)
  point P42 (24, 27.9824)
  point P43 (24, 14.75)
  point P44 (-24, 27.9824)
  point P45 (-24, 14.75)
  point P4 (-10.075, 0)
  point P11 (70.075, 14.75)
  point P15 (70.075, 27.9824)
  point P27 (12.5, 18.4793)
  point P38 (-19.5, 18.4793)
  point P23 (16, 20.5)
  point P5 (10.075, 62.3598)
  point P8 (-10.075, 64.0764)
  horizontal L1
  perpendicular L1 L2
  perpendicular L1 L3
  horizontal P1 P7
  horizontal P1 P6
  coincident L2 P9
  coincident L3 P10
  perpendicular L3 L4
  perpendicular L2 L5
  perpendicular L4 L6
  coincident P2 L6
  coincident P14 L6
  coincident L6 P16
  perpendicular L3 L8
  coincident L6 P19
  perpendicular L3 L9
  horizontal L7
  perpendicular L7 L10
  coincident P18 P21
  coincident P20 L10
  coincident P17 L10
  coincident P3 L10
  coincident P13 L10
  concentric C1 C2
  coincident P22 P30
  vertical L16
  concentric C3 C4
  coincident P31 P39
  vertical L18
  coincident P36 P40
  coincident P22 P41
  horizontal L23
  coincident L8 P42
  coincident L4 P43
  perpendicular L4 L24
  coincident L8 P44
  coincident L4 P45
  perpendicular L4 L25
  dimension "d182" distance L1 P4 = 15
  dimension "d185" distance P2 P14 = 1.15 (= "belt_pdo_toothside")
  dimension "d186" distance P2 P11 = 0.25 (= "belt_pdo_backside")
  dimension "d187" distance P15 P19 = 0.25 (= "belt_pdo_backside")
  dimension "d188" distance P16 P19 = 1.15 (= "belt_pdo_toothside")
  dimension "d189" distance P3 P20 = 12.7324 (= "( 20 * 2 / PI ) * 1 mm")
  dimension "d190" diameter C2 = 8
  dimension "d191" diameter C1 = 4.75
  dimension "d192" distance P27 L16 = 7 (= "hw_m4hex_d")
  dimension "d193" diameter C4 = 8
  dimension "d194" diameter C3 = 4.75
  dimension "d195" distance P38 L18 = 7 (= "hw_m4hex_d")
  dimension "d196" distance P23 L24 = 8
  dimension "d197" distance P31 P45 = 8
  dimension "d198" distance P42 L25 = 48
  dimension "d199" distance P1 P23 = 16
  dimension "d200" distance P1 P31 = 16 (= "d199")
  dimension "d201" distance L1 L23 = 5.5
  dimension "d320" distance P5 L6 = 60
  dimension "d321" distance P8 L10 = 20
extrude "Extrude14" sketch "Facing" profile of L1 L3 L4 L10 L11 L12 L18 L19 L21 L22 C2 L23 L24 L25 L26 L27 L43 L44 L45 L46 L48 L49 L50 L51 to an object
extrude "Extrude15" sketch "Facing" profile of L1 L2 L10 L28 C4 L29 L30 L31 L32 L33 L35 L36 L37 L38 L39 L40 L41 L46 L47 blind -0.25
extrude "Extrude16" add sketch "Facing" profile of L1 L3 L4 L11 L12 L19 L21 L22 C2 L23 L24 L25 L26 L27 L43 L44 L45 L48 L49 L50 L51 to an object from offset 26
sketch "Z Belt Taper" plane through (0, 0, 0) normal (0, 1, 0) x axis (1, 0, 0)
  line L1 (13.5, -16.15) -> (13.5, -15)
  line L2 (22.5, -16.15) -> (13.5, -16.15)
  line L3 (22.5, -15) -> (22.5, -16.15)
  line L4 (12.075, -15) -> (22.85, -15)
  line L5 (10.075, -14.75) -> (23.35, -14.75)
  line L6 (22.85, -26) -> (22.85, -15)
  line L7 (18.325, -24.5) -> (10.075, -16.25)
  line L8 (12.075, -18.1086) -> (12.075, -15)
  line L9 (19.9664, -26) -> (12.075, -18.1086)
  line L10 (11.575, -17.75) -> (11.575, -14.75)
  line L11 (10.075, -26) -> (10.075, -14.75)
  line L12 (10.075, -14.75) -> (10.075, -26)
  line L13 (18.325, -26) -> (10.075, -26)
  line L14 (22.85, -26) -> (19.9664, -26)
  line L15 (18.325, -24.5) -> (18.325, -26)
  line L16 (14, -16.65) -> (12.35, -15)
  line L17 (12.075, -16.65) -> (14, -16.65)
  point P6 (18, -16.15)
  point P2 (13.5, -15)
  point P5 (22.5, -15)
  point P16 (11.575, -14.75)
  point P17 (11.575, -17.75)
  point P13 (10.075, -16.25)
  point P11 (22.85, -26)
  point P21 (22.85, -26)
  point P19 (10.075, -26)
  point P20 (10.075, -26)
  point P22 (18.325, -26)
  point P24 (12.35, -15)
  point P3 (13.5, -16.15)
  point P26 (12.075, -16.65)
  point P4 (22.5, -16.15)
  point P1 (0, 0)
  point P9 (23.35, -14.75)
  point P10 (10.075, -14.75)
  point P18 (10.075, -14.75)
  point P23 (18.325, -24.5)
  point P25 (14, -16.65)
  vertical L1
  perpendicular L1 L2
  perpendicular L2 L3
  midpoint L2 P6
  horizontal L4
  coincident P2 L4
  coincident P5 L4
  vertical L6
  perpendicular L4 L8
  parallel L7 L9
  coincident L5 P16
  coincident L7 P17
  perpendicular L5 L10
  coincident P13 L12
  perpendicular L12 L13
  horizontal L14
  coincident P11 P21
  perpendicular L13 L15
  coincident P19 P20
  coincident L14 P22
  coincident L4 P24
  coincident P3 L16
  parallel L7 L16
  coincident L8 P26
  perpendicular L8 L17
  dimension "d212" distance P3 P4 = 9
  dimension "d213" distance P1 P6 = 18
  dimension "d214" distance P2 P3 = 1.15 (= "belt_pdo_toothside")
  dimension "d216" distance L4 P9 = 0.25 (= "belt_pdo_backside")
  dimension "d217" distance P9 L6 = 0.5
  dimension "d219" distance L7 L9 = 0.1
  dimension "d225" angle L7 L12 = 45
  dimension "d226" distance P10 P16 = 1.5
  dimension "d227" distance L8 P18 = 2
  dimension "d228" distance P22 P23 = 1.5
  dimension "d229" distance P10 P13 = 1.5
  dimension "d245" distance P3 P25 = 0.5
extrude "Extrude17" sketch "Z Belt Taper" profile of L5 L7 L10 L11 L12 L13 L15 to an object
extrude "Extrude18" sketch "Z Belt Taper" profile of L5 L7 L10 L11 L12 L13 L15 to an object
extrude "Extrude19" sketch "Z Belt Taper" profile of L4 L6 L8 L9 L14 to an object bodies "YLB Z Belt Clamp"
sketch "Z Belt Profile" plane through (22.85, 0, 0) normal (1, 0, 0) x axis (0, 1, 0)
  line L1 (-24, 15) -> (-24, 26)
  line L2 (24, 15) -> (-24, 15)
  line L3 (24, 26) -> (24, 15)
  line L4 (-24, 26) -> (24, 26)
  line L5 (23, 16.15) -> (24, 16.15)
  line L6 (23, 15.4) -> (23, 16.15)
  line L7 (23.2607, 15.4) -> (23, 15.4)
  line L8 (23, 15) -> (23, 15.4)
  arc A1 centre (24, 15.6) radius 0.55 clockwise from (23.5111, 15.852) to (24, 16.15)
  arc A2 centre (24.4, 15.3938) radius 1 clockwise from (23.4093, 15.5296) to (23.5111, 15.852)
  arc A3 centre (23.2607, 15.55) radius 0.15 clockwise from (23.4093, 15.5296) to (23.2607, 15.4)
  point P6 (24, 16.15)
  point P9 (24, 15.6)
  point P15 (23, 15)
  point P7 (23, 16.15)
  point P11 (24.4, 15.3938)
  point P4 (24, 15)
  point P8 (23, 15.4)
  coincident L3 P6
  perpendicular L3 L5
  perpendicular L2 L6
  coincident L3 P9
  tangent A1 A2
  tangent A2 A3
  horizontal L7
  tangent A3 L7
  coincident L2 P15
  perpendicular L2 L8
  dimension "d246" distance P6 P7 = 1
  dimension "d253" radius A1 = 0.55
  dimension "d254" radius A2 = 1
  dimension "d255" distance L3 P11 = 0.4
  dimension "d256" radius A3 = 0.15
  dimension "d257" distance P4 L5 = 1.15 (= "belt_pdo_toothside")
  dimension "d258" distance P7 P8 = 0.75
extrude "Extrude21" new body sketch "Z Belt Profile" profile of L2 L3 A1 A2 A3 L7 L8 to an object
mirror "Mirror2" mirrorStitchTolerance 0.1
rectangular_pattern "R-Pattern2" countU 24 uSpaceDistance -2 vSpaceDistance 0
combine "Combine3"
extrude "Extrude23" sketch "Z Belt Guide" profile of C1 C3 to an object
extrude "Extrude24" sketch "Z Belt Guide" profile of C1 L11 L12 L13 L14 L15 L16 L17 L18 L19 L20 L21 L22 C3 to an object from offset -19
chamfer "Chamfer8" distance 1.8
sketch "Face Adjust" plane through (0, 0, 14.75) normal (0, 0, 1) x axis (-1, 0, 0)
  line L1 (-11.575, -10.075) -> (-11.575, -24)
  line L2 (-23.35, -10.075) -> (-11.575, -10.075)
  line L3 (-23.35, -42.5) -> (-23.35, -10.075)
  line L4 (-10.075, -42.5) -> (-23.35, -42.5)
  line L5 (-10.075, -24) -> (-10.075, -42.5)
  line L6 (-11.575, -24) -> (-10.075, -24)
  line L7 (-23.35, -24) -> (-11.575, -24)
  point P2 (-11.575, -24)
  point P8 (-11.575, -24)
  point P9 (-23.35, -24)
  coincident P2 P8
  coincident L3 P9
  perpendicular L3 L7
extrude "Extrude25" cut sketch "Face Adjust" profile of L3 L4 L5 L6 L7 to an object
extrude "Extrude26" new body sketch "Facing" profile of L5 L7 L8 L13 L14 L15 L16 L17 along normal blind 20 bodies "YLF Y Belt Clamp"
extrude "Extrude31" cut sketch "Facing" profile of L22 C2 L23 L24 L25 L26 L27 to an object taper 1 from offset 2.5
extrude "Extrude32" cut sketch "Facing" profile of L28 C4 L29 L30 L31 L32 L33 to an object from offset 2.5
sketch "Y Belt Teeth" plane through (0, 22.5, 0) normal (0, 1, 0) x axis (-1, 0, 0)
  line L1 (13.15, 0) -> (12, 0)
  line L2 (13.15, 20) -> (13.15, 0)
  line L3 (12, 20) -> (13.15, 20)
  line L4 (12, 0) -> (12, 20)
  line L5 (13.15, 1) -> (12, 1)
  line L6 (12.4, 1) -> (12.4, 0)
  arc A1 centre (12.6, 0) radius 0.55 clockwise from (12.852, 0.4889) to (13.15, 0)
  arc A2 centre (12.3938, -0.4) radius 1 clockwise from (12.5296, 0.5907) to (12.852, 0.4889)
  arc A3 centre (12.55, 0.7393) radius 0.15 clockwise from (12.5296, 0.5907) to (12.4, 0.7393)
  point P6 (12, 1)
  point P7 (13.15, 1)
  point P8 (12.4, 0)
  point P9 (12.4, 1)
  point P11 (13.15, 0)
  point P10 (12.6, 0)
  point P3 (13.15, 0)
  point P15 (12.4, 0.7393)
  point P13 (12.3938, -0.4)
  coincident L4 P6
  coincident L2 P7
  perpendicular L2 L5
  coincident L1 P8
  coincident L5 P9
  perpendicular L5 L6
  coincident L1 P11
  coincident L1 P10
  coincident P3 P11
  tangent A1 A2
  tangent L6 A3
  coincident L6 P15
  tangent A2 A3
  dimension "d299" distance P3 L5 = 1
  dimension "d300" distance P3 L6 = 0.75
  dimension "d301" radius A1 = 0.55
  dimension "d302" distance L1 P13 = 0.4
  dimension "d303" radius A2 = 1
  dimension "d304" radius A3 = 0.15
extrude "Extrude30" new body sketch "Y Belt Teeth" profile of L2 L5 L6 A1 A2 A3 to an object
mirror "Mirror3" mirrorStitchTolerance 0.1
rectangular_pattern "R-Pattern3" countU 10 uSpaceDistance 2 vSpaceDistance 0
combine "Combine4"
